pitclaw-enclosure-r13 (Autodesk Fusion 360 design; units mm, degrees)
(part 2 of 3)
extrude "Extrude8" new body sketch "J2 contact 5 profile" blind 0.12 from offset 11.78 bodies "J2 contact 5"
sketch "J2 contact 6 profile" plane through (0, 0, 0) normal (0, 0, 1) x axis (1, 0, 0)
  line L1 (22.135, 49.05) -> (21.865, 49.05)
  line L2 (22.175, 51.51) -> (22.175, 49.09)
  line L3 (21.865, 51.55) -> (22.135, 51.55)
  line L4 (21.825, 49.09) -> (21.825, 51.51)
  arc A1 centre (22.135, 49.09) radius 0.04 clockwise from (22.175, 49.09) to (22.135, 49.05)
  arc A2 centre (22.135, 51.51) radius 0.04 clockwise from (22.135, 51.55) to (22.175, 51.51)
  arc A3 centre (21.865, 51.51) radius 0.04 clockwise from (21.825, 51.51) to (21.865, 51.55)
  arc A4 centre (21.865, 49.09) radius 0.04 clockwise from (21.865, 49.05) to (21.825, 49.09)
extrude "Extrude9" new body sketch "J2 contact 6 profile" blind 0.12 from offset 11.78 bodies "J2 contact 6"
sketch "J2 contact 7 profile" plane through (0, 0, 0) normal (0, 0, 1) x axis (1, 0, 0)
  line L1 (23.155, 49.05) -> (22.885, 49.05)
  line L2 (23.195, 51.51) -> (23.195, 49.09)
  line L3 (22.885, 51.55) -> (23.155, 51.55)
  line L4 (22.845, 49.09) -> (22.845, 51.51)
  arc A1 centre (23.155, 49.09) radius 0.04 clockwise from (23.195, 49.09) to (23.155, 49.05)
  arc A2 centre (23.155, 51.51) radius 0.04 clockwise from (23.155, 51.55) to (23.195, 51.51)
  arc A3 centre (22.885, 51.51) radius 0.04 clockwise from (22.845, 51.51) to (22.885, 51.55)
  arc A4 centre (22.885, 49.09) radius 0.04 clockwise from (22.885, 49.05) to (22.845, 49.09)
extrude "Extrude10" new body sketch "J2 contact 7 profile" blind 0.12 from offset 11.78 bodies "J2 contact 7"
sketch "J2 contact 8 profile" plane through (0, 0, 0) normal (0, 0, 1) x axis (1, 0, 0)
  line L1 (24.175, 49.05) -> (23.905, 49.05)
  line L2 (24.215, 51.51) -> (24.215, 49.09)
  line L3 (23.905, 51.55) -> (24.175, 51.55)
  line L4 (23.865, 49.09) -> (23.865, 51.51)
  arc A1 centre (24.175, 49.09) radius 0.04 clockwise from (24.215, 49.09) to (24.175, 49.05)
  arc A2 centre (24.175, 51.51) radius 0.04 clockwise from (24.175, 51.55) to (24.215, 51.51)
  arc A3 centre (23.905, 51.51) radius 0.04 clockwise from (23.865, 51.51) to (23.905, 51.55)
  arc A4 centre (23.905, 49.09) radius 0.04 clockwise from (23.905, 49.05) to (23.865, 49.09)
extrude "Extrude11" new body sketch "J2 contact 8 profile" blind 0.12 from offset 11.78 bodies "J2 contact 8"
sketch "J2 leads profile" plane through (0, 0, 0) normal (0, 0, 1) x axis (1, 0, 0)
  circle C1 centre (16.94, 44.38) radius 0.275
  circle C2 centre (17.956, 42.6) radius 0.275
  circle C3 centre (18.972, 44.38) radius 0.275
  circle C4 centre (19.988, 42.6) radius 0.275
  circle C5 centre (21.004, 44.38) radius 0.275
  circle C6 centre (22.02, 42.6) radius 0.275
  circle C7 centre (23.036, 44.38) radius 0.275
  circle C8 centre (24.052, 42.6) radius 0.275
extrude "Extrude12" new body sketch "J2 leads profile" blind 3.5 from offset 6.5 bodies "J2 leads", "J2 leads (1)", "J2 leads (2)", "J2 leads (3)", "J2 leads (4)", "J2 leads (5)", "J2 leads (6)", "J2 leads (7)"
sketch "J9 barrel housing profile" plane through (0, 0, 0) normal (0, 0, 1) x axis (1, 0, 0)
  line L1 (7.85, 37.6) -> (-0.85, 37.6)
  line L2 (8, 51.85) -> (8, 37.75)
  line L3 (-0.85, 52) -> (7.85, 52)
  line L4 (-1, 37.75) -> (-1, 51.85)
  arc A1 centre (7.85, 37.75) radius 0.15 clockwise from (8, 37.75) to (7.85, 37.6)
  arc A2 centre (7.85, 51.85) radius 0.15 clockwise from (7.85, 52) to (8, 51.85)
  arc A3 centre (-0.85, 51.85) radius 0.15 clockwise from (-1, 51.85) to (-0.85, 52)
  arc A4 centre (-0.85, 37.75) radius 0.15 clockwise from (-0.85, 37.6) to (-1, 37.75)
extrude "Extrude1" new body sketch "J9 barrel housing profile" blind 10.8 from offset 9.1 bodies "J9 barrel housing"
sketch "J9 barrel opening profile" plane through (0, 0, 0) normal (0, 1, 0) x axis (1, 0, 0)
  circle C1 centre (3.5, -15.6) radius 3.15
extrude "Extrude2" cut sketch "J9 barrel opening profile" blind 3.55 from offset 48.5
sketch "J9 center pin profile" plane through (0, 0, 0) normal (0, 1, 0) x axis (1, 0, 0)
  circle C1 centre (3.5, -15.6) radius 1.05
extrude "Extrude3" new body sketch "J9 center pin profile" blind 2.6 from offset 49 bodies "J9 center pin"
sketch "J9 leads profile" plane through (0, 0, 0) normal (0, 0, 1) x axis (1, 0, 0)
  circle C1 centre (3.5, 38.4) radius 0.325
  circle C2 centre (3.5, 44.3) radius 0.325
  circle C3 centre (-1.2, 41.2) radius 0.325
extrude "Extrude4" new body sketch "J9 leads profile" blind 3.5 from offset 6.5 bodies "J9 leads", "J9 leads (1)", "J9 leads (2)"
sketch "J4 jack housing profile" plane through (0, 0, 0) normal (0, 0, 1) x axis (1, 0, 0)
  line L1 (19.4, -41.5) -> (14.6, -41.5)
  line L2 (19.55, -33.65) -> (19.55, -41.35)
  line L3 (14.6, -33.5) -> (19.4, -33.5)
  line L4 (14.45, -41.35) -> (14.45, -33.65)
  arc A1 centre (19.4, -41.35) radius 0.15 clockwise from (19.55, -41.35) to (19.4, -41.5)
  arc A2 centre (19.4, -33.65) radius 0.15 clockwise from (19.4, -33.5) to (19.55, -33.65)
  arc A3 centre (14.6, -33.65) radius 0.15 clockwise from (14.45, -33.65) to (14.6, -33.5)
  arc A4 centre (14.6, -41.35) radius 0.15 clockwise from (14.6, -41.5) to (14.45, -41.35)
extrude "Extrude1" new body sketch "J4 jack housing profile" blind 5.1 from offset 9.1 bodies "J4 jack housing"
sketch "J4 front collar profile" plane through (0, 0, 0) normal (0, 1, 0) x axis (1, 0, 0)
  circle C1 centre (17, -11.65) radius 2
extrude "Extrude2" new body sketch "J4 front collar profile" blind 3.1 from offset -44.5 bodies "J4 front collar"
sketch "J4 2.5mm plug bore profile" plane through (0, 0, 0) normal (0, 1, 0) x axis (1, 0, 0)
  circle C1 centre (17, -11.65) radius 1.25
extrude "Extrude3" cut sketch "J4 2.5mm plug bore profile" blind 3.3 from offset -44.52
sketch "J4 leads profile" plane through (0, 0, 0) normal (0, 0, 1) x axis (1, 0, 0)
  circle C1 centre (17, -33.4) radius 0.275
  circle C2 centre (18.8, -35.5) radius 0.275
  circle C3 centre (15.2, -35.5) radius 0.275
extrude "Extrude4" new body sketch "J4 leads profile" blind 3.5 from offset 6.5 bodies "J4 leads", "J4 leads (1)", "J4 leads (2)"
sketch "J5 jack housing profile" plane through (0, 0, 0) normal (0, 0, 1) x axis (1, 0, 0)
  line L1 (2.4, -41.5) -> (-2.4, -41.5)
  line L2 (2.55, -33.65) -> (2.55, -41.35)
  line L3 (-2.4, -33.5) -> (2.4, -33.5)
  line L4 (-2.55, -41.35) -> (-2.55, -33.65)
  arc A1 centre (2.4, -41.35) radius 0.15 clockwise from (2.55, -41.35) to (2.4, -41.5)
  arc A2 centre (2.4, -33.65) radius 0.15 clockwise from (2.4, -33.5) to (2.55, -33.65)
  arc A3 centre (-2.4, -33.65) radius 0.15 clockwise from (-2.55, -33.65) to (-2.4, -33.5)
  arc A4 centre (-2.4, -41.35) radius 0.15 clockwise from (-2.4, -41.5) to (-2.55, -41.35)
extrude "Extrude1" new body sketch "J5 jack housing profile" blind 5.1 from offset 9.1 bodies "J5 jack housing"
sketch "J5 front collar profile" plane through (0, 0, 0) normal (0, 1, 0) x axis (1, 0, 0)
  circle C1 centre (0, -11.65) radius 2
extrude "Extrude2" new body sketch "J5 front collar profile" blind 3.1 from offset -44.5 bodies "J5 front collar"
sketch "J5 2.5mm plug bore profile" plane through (0, 0, 0) normal (0, 1, 0) x axis (1, 0, 0)
  circle C1 centre (0, -11.65) radius 1.25
extrude "Extrude3" cut sketch "J5 2.5mm plug bore profile" blind 3.3 from offset -44.52
sketch "J5 leads profile" plane through (0, 0, 0) normal (0, 0, 1) x axis (1, 0, 0)
  circle C1 centre (0, -33.4) radius 0.275
  circle C2 centre (1.8, -35.5) radius 0.275
  circle C3 centre (-1.8, -35.5) radius 0.275
extrude "Extrude4" new body sketch "J5 leads profile" blind 3.5 from offset 6.5 bodies "J5 leads", "J5 leads (1)", "J5 leads (2)"
sketch "J6 jack housing profile" plane through (0, 0, 0) normal (0, 0, 1) x axis (1, 0, 0)
  line L1 (-14.6, -41.5) -> (-19.4, -41.5)
  line L2 (-14.45, -33.65) -> (-14.45, -41.35)
  line L3 (-19.4, -33.5) -> (-14.6, -33.5)
  line L4 (-19.55, -41.35) -> (-19.55, -33.65)
  arc A1 centre (-14.6, -41.35) radius 0.15 clockwise from (-14.45, -41.35) to (-14.6, -41.5)
  arc A2 centre (-14.6, -33.65) radius 0.15 clockwise from (-14.6, -33.5) to (-14.45, -33.65)
  arc A3 centre (-19.4, -33.65) radius 0.15 clockwise from (-19.55, -33.65) to (-19.4, -33.5)
  arc A4 centre (-19.4, -41.35) radius 0.15 clockwise from (-19.4, -41.5) to (-19.55, -41.35)
extrude "Extrude1" new body sketch "J6 jack housing profile" blind 5.1 from offset 9.1 bodies "J6 jack housing"
sketch "J6 front collar profile" plane through (0, 0, 0) normal (0, 1, 0) x axis (1, 0, 0)
  circle C1 centre (-17, -11.65) radius 2
extrude "Extrude2" new body sketch "J6 front collar profile" blind 3.1 from offset -44.5 bodies "J6 front collar"
sketch "J6 2.5mm plug bore profile" plane through (0, 0, 0) normal (0, 1, 0) x axis (1, 0, 0)
  circle C1 centre (-17, -11.65) radius 1.25
extrude "Extrude3" cut sketch "J6 2.5mm plug bore profile" blind 3.3 from offset -44.52
sketch "J6 leads profile" plane through (0, 0, 0) normal (0, 0, 1) x axis (1, 0, 0)
  circle C1 centre (-17, -33.4) radius 0.275
  circle C2 centre (-15.2, -35.5) radius 0.275
  circle C3 centre (-18.8, -35.5) radius 0.275
extrude "Extrude4" new body sketch "J6 leads profile" blind 3.5 from offset 6.5 bodies "J6 leads", "J6 leads (1)", "J6 leads (2)"
sketch "J8 female socket profile" plane through (0, 0, 0) normal (0, 0, 1) x axis (1, 0, 0)
  line L1 (18.12, -9.77) -> (-6.98, -9.77)
  line L2 (18.27, -7.38) -> (18.27, -9.62)
  line L3 (-6.98, -7.23) -> (18.12, -7.23)
  line L4 (-7.13, -9.62) -> (-7.13, -7.38)
  arc A1 centre (18.12, -9.62) radius 0.15 clockwise from (18.27, -9.62) to (18.12, -9.77)
  arc A2 centre (18.12, -7.38) radius 0.15 clockwise from (18.12, -7.23) to (18.27, -7.38)
  arc A3 centre (-6.98, -7.38) radius 0.15 clockwise from (-7.13, -7.38) to (-6.98, -7.23)
  arc A4 centre (-6.98, -9.62) radius 0.15 clockwise from (-6.98, -9.77) to (-7.13, -9.62)
extrude "Extrude1" new body sketch "J8 female socket profile" blind 8.5 from offset 9.1 bodies "J8 female socket"
sketch "J8 socket receptacles profile" plane through (0, 0, 0) normal (0, 0, 1) x axis (1, 0, 0)
  circle C1 centre (17, -8.5) radius 0.575
  circle C2 centre (14.46, -8.5) radius 0.575
  circle C3 centre (11.92, -8.5) radius 0.575
  circle C4 centre (9.38, -8.5) radius 0.575
  circle C5 centre (6.84, -8.5) radius 0.575
  circle C6 centre (4.3, -8.5) radius 0.575
  circle C7 centre (1.76, -8.5) radius 0.575
  circle C8 centre (-0.78, -8.5) radius 0.575
  circle C9 centre (-3.32, -8.5) radius 0.575
  circle C10 centre (-5.86, -8.5) radius 0.575
extrude "Extrude2" cut sketch "J8 socket receptacles profile" blind 0.82 from offset 16.8
sketch "ADS1115 blue module PCB profile" plane through (0, 0, 0) normal (0, 0, 1) x axis (1, 0, 0)
  line L1 (19.24, -24) -> (-8.16, -24)
  line L2 (19.54, -7.3) -> (19.54, -23.7)
  line L3 (-8.16, -7) -> (19.24, -7)
  line L4 (-8.46, -23.7) -> (-8.46, -7.3)
  arc A1 centre (19.24, -23.7) radius 0.3 clockwise from (19.54, -23.7) to (19.24, -24)
  arc A2 centre (19.24, -7.3) radius 0.3 clockwise from (19.24, -7) to (19.54, -7.3)
  arc A3 centre (-8.16, -7.3) radius 0.3 clockwise from (-8.46, -7.3) to (-8.16, -7)
  arc A4 centre (-8.16, -23.7) radius 0.3 clockwise from (-8.16, -24) to (-8.46, -23.7)
extrude "Extrude3" new body sketch "ADS1115 blue module PCB profile" blind 1.6 from offset 17.6 bodies "ADS1115 blue module PCB"
sketch "ADS1115 IC visual body profile" plane through (0, 0, 0) normal (0, 0, 1) x axis (1, 0, 0)
  line L1 (7.92, -19.5) -> (3.16, -19.5)
  line L2 (8.04, -15.62) -> (8.04, -19.38)
  line L3 (3.16, -15.5) -> (7.92, -15.5)
  line L4 (3.04, -19.38) -> (3.04, -15.62)
  arc A1 centre (7.92, -19.38) radius 0.12 clockwise from (8.04, -19.38) to (7.92, -19.5)
  arc A2 centre (7.92, -15.62) radius 0.12 clockwise from (7.92, -15.5) to (8.04, -15.62)
  arc A3 centre (3.16, -15.62) radius 0.12 clockwise from (3.04, -15.62) to (3.16, -15.5)
  arc A4 centre (3.16, -19.38) radius 0.12 clockwise from (3.16, -19.5) to (3.04, -19.38)
extrude "Extrude4" new body sketch "ADS1115 IC visual body profile" blind 1.2 from offset 19.2 bodies "ADS1115 IC visual body"
sketch "ADC header pin profile" plane through (0, 0, 0) normal (0, 0, 1) x axis (1, 0, 0)
  circle C1 centre (17, -8.5) radius 0.32
extrude "Extrude5" new body sketch "ADC header pin profile" blind 12.5 from offset 7 bodies "ADC header pin"
sketch "ADC header pin profile (1)" plane through (0, 0, 0) normal (0, 0, 1) x axis (1, 0, 0)
  circle C1 centre (14.46, -8.5) radius 0.32
extrude "Extrude6" new body sketch "ADC header pin profile (1)" blind 12.5 from offset 7 bodies "ADC header pin (1)"
sketch "ADC header pin profile (2)" plane through (0, 0, 0) normal (0, 0, 1) x axis (1, 0, 0)
  circle C1 centre (11.92, -8.5) radius 0.32
extrude "Extrude7" new body sketch "ADC header pin profile (2)" blind 12.5 from offset 7 bodies "ADC header pin (2)"
sketch "ADC header pin profile (3)" plane through (0, 0, 0) normal (0, 0, 1) x axis (1, 0, 0)
  circle C1 centre (9.38, -8.5) radius 0.32
extrude "Extrude8" new body sketch "ADC header pin profile (3)" blind 12.5 from offset 7 bodies "ADC header pin (3)"
sketch "ADC header pin profile (4)" plane through (0, 0, 0) normal (0, 0, 1) x axis (1, 0, 0)
  circle C1 centre (6.84, -8.5) radius 0.32
extrude "Extrude9" new body sketch "ADC header pin profile (4)" blind 12.5 from offset 7 bodies "ADC header pin (4)"
sketch "ADC header pin profile (5)" plane through (0, 0, 0) normal (0, 0, 1) x axis (1, 0, 0)
  circle C1 centre (4.3, -8.5) radius 0.32
extrude "Extrude10" new body sketch "ADC header pin profile (5)" blind 12.5 from offset 7 bodies "ADC header pin (5)"
sketch "ADC header pin profile (6)" plane through (0, 0, 0) normal (0, 0, 1) x axis (1, 0, 0)
  circle C1 centre (1.76, -8.5) radius 0.32
extrude "Extrude11" new body sketch "ADC header pin profile (6)" blind 12.5 from offset 7 bodies "ADC header pin (6)"
sketch "ADC header pin profile (7)" plane through (0, 0, 0) normal (0, 0, 1) x axis (1, 0, 0)
  circle C1 centre (-0.78, -8.5) radius 0.32
extrude "Extrude12" new body sketch "ADC header pin profile (7)" blind 12.5 from offset 7 bodies "ADC header pin (7)"
sketch "ADC header pin profile (8)" plane through (0, 0, 0) normal (0, 0, 1) x axis (1, 0, 0)
  circle C1 centre (-3.32, -8.5) radius 0.32
extrude "Extrude13" new body sketch "ADC header pin profile (8)" blind 12.5 from offset 7 bodies "ADC header pin (8)"
sketch "ADC header pin profile (9)" plane through (0, 0, 0) normal (0, 0, 1) x axis (1, 0, 0)
  circle C1 centre (-5.86, -8.5) radius 0.32
extrude "Extrude14" new body sketch "ADC header pin profile (9)" blind 12.5 from offset 7 bodies "ADC header pin (9)"
sketch "Adafruit5807 PCB profile" plane through (0, 0, 0) normal (0, 0, 1) x axis (1, 0, 0)
  line L1 (-4.54, 25.362) -> (-24.46, 25.362)
  line L2 (-4.34, 48.657) -> (-4.34, 25.562)
  line L3 (-24.46, 48.857) -> (-4.54, 48.857)
  line L4 (-24.66, 25.562) -> (-24.66, 48.657)
  arc A1 centre (-4.54, 25.562) radius 0.2 clockwise from (-4.34, 25.562) to (-4.54, 25.362)
  arc A2 centre (-4.54, 48.657) radius 0.2 clockwise from (-4.54, 48.857) to (-4.34, 48.657)
  arc A3 centre (-24.46, 48.657) radius 0.2 clockwise from (-24.66, 48.657) to (-24.46, 48.857)
  arc A4 centre (-24.46, 25.562) radius 0.2 clockwise from (-24.46, 25.362) to (-24.66, 25.562)
extrude "Extrude1" new body sketch "Adafruit5807 PCB profile" blind 1.6 from offset 12.1 bodies "Adafruit5807 PCB"
sketch "5807 M2 mounting holes profile" plane through (0, 0, 0) normal (0, 0, 1) x axis (1, 0, 0)
  circle C1 centre (-6.753, 46.317) radius 1.25
  circle C2 centre (-21.993, 46.317) radius 1.25
extrude "Extrude2" cut sketch "5807 M2 mounting holes profile" blind 1.64 from offset 12.08
sketch "3mm nylon spacer profile" plane through (0, 0, 0) normal (0, 0, 1) x axis (1, 0, 0)
  circle C1 centre (-6.753, 46.317) radius 2.5
extrude "Extrude3" new body sketch "3mm nylon spacer profile" blind 3 from offset 9.1 bodies "3mm nylon spacer"
sketch "M2 head washer profile" plane through (0, 0, 0) normal (0, 0, 1) x axis (1, 0, 0)
  circle C1 centre (-6.753, 46.317) radius 2.5
extrude "Extrude4" new body sketch "M2 head washer profile" blind 0.3 from offset 13.7 bodies "M2 head washer"
sketch "M2 screw head profile" plane through (0, 0, 0) normal (0, 0, 1) x axis (1, 0, 0)
  circle C1 centre (-6.753, 46.317) radius 2
extrude "Extrude5" new body sketch "M2 screw head profile" blind 1.5 from offset 14 bodies "M2 screw head"
sketch "3mm nylon spacer profile (1)" plane through (0, 0, 0) normal (0, 0, 1) x axis (1, 0, 0)
  circle C1 centre (-21.993, 46.317) radius 2.5
extrude "Extrude6" new body sketch "3mm nylon spacer profile (1)" blind 3 from offset 9.1 bodies "3mm nylon spacer (1)"
sketch "M2 head washer profile (1)" plane through (0, 0, 0) normal (0, 0, 1) x axis (1, 0, 0)
  circle C1 centre (-21.993, 46.317) radius 2.5
extrude "Extrude7" new body sketch "M2 head washer profile (1)" blind 0.3 from offset 13.7 bodies "M2 head washer (1)"
sketch "M2 screw head profile (1)" plane through (0, 0, 0) normal (0, 0, 1) x axis (1, 0, 0)
  circle C1 centre (-21.993, 46.317) radius 2
extrude "Extrude8" new body sketch "M2 screw head profile (1)" blind 1.5 from offset 14 bodies "M2 screw head (1)"
sketch "USB-C metal shell profile" plane through (0, 0, 0) normal (0, 1, 0) x axis (1, 0, 0)
  line L1 (-11.23, -13.6) -> (-17.77, -13.6)
  line L2 (-10.03, -15.6) -> (-10.03, -14.8)
  line L3 (-17.77, -16.8) -> (-11.23, -16.8)
  line L4 (-18.97, -14.8) -> (-18.97, -15.6)
  arc A1 centre (-11.23, -14.8) radius 1.2 clockwise from (-11.23, -13.6) to (-10.03, -14.8)
  arc A2 centre (-11.23, -15.6) radius 1.2 clockwise from (-10.03, -15.6) to (-11.23, -16.8)
  arc A3 centre (-17.77, -15.6) radius 1.2 clockwise from (-17.77, -16.8) to (-18.97, -15.6)
  arc A4 centre (-17.77, -14.8) radius 1.2 clockwise from (-18.97, -14.8) to (-17.77, -13.6)
extrude "Extrude9" new body sketch "USB-C metal shell profile" blind 7.5 from offset 42.5 bodies "USB-C metal shell"
sketch "USB-C mouth profile" plane through (0, 0, 0) normal (0, 1, 0) x axis (1, 0, 0)
  line L1 (-11.65, -14.2) -> (-17.35, -14.2)
  line L2 (-10.75, -15.3) -> (-10.75, -15.1)
  line L3 (-17.35, -16.2) -> (-11.65, -16.2)
  line L4 (-18.25, -15.1) -> (-18.25, -15.3)
  arc A1 centre (-11.65, -15.1) radius 0.9 clockwise from (-11.65, -14.2) to (-10.75, -15.1)
  arc A2 centre (-11.65, -15.3) radius 0.9 clockwise from (-10.75, -15.3) to (-11.65, -16.2)
  arc A3 centre (-17.35, -15.3) radius 0.9 clockwise from (-17.35, -16.2) to (-18.25, -15.3)
  arc A4 centre (-17.35, -15.1) radius 0.9 clockwise from (-18.25, -15.1) to (-17.35, -14.2)
extrude "Extrude10" cut sketch "USB-C mouth profile" blind 2.02 from offset 48
sketch "USB-C inner tongue profile" plane through (0, 0, 0) normal (0, 0, 1) x axis (1, 0, 0)
  line L1 (-11.52, 48.1) -> (-17.48, 48.1)
  line L2 (-11.4, 49.78) -> (-11.4, 48.22)
  line L3 (-17.48, 49.9) -> (-11.52, 49.9)
  line L4 (-17.6, 48.22) -> (-17.6, 49.78)
  arc A1 centre (-11.52, 48.22) radius 0.12 clockwise from (-11.4, 48.22) to (-11.52, 48.1)
  arc A2 centre (-11.52, 49.78) radius 0.12 clockwise from (-11.52, 49.9) to (-11.4, 49.78)
  arc A3 centre (-17.48, 49.78) radius 0.12 clockwise from (-17.6, 49.78) to (-17.48, 49.9)
  arc A4 centre (-17.48, 48.22) radius 0.12 clockwise from (-17.48, 48.1) to (-17.6, 48.22)
extrude "Extrude11" new body sketch "USB-C inner tongue profile" blind 0.5 from offset 14.95 bodies "USB-C inner tongue"
position "Position1"
sketch "Probe recess backing profile" plane through (0, 0, 0) normal (0, 1, 0) x axis (1, 0, 0)
  line L1 (28, -1.65) -> (-28, -1.65)
  line L2 (32, -17.65) -> (32, -5.65)
  line L3 (-28, -21.65) -> (28, -21.65)
  line L4 (-32, -5.65) -> (-32, -17.65)
  arc A1 centre (28, -5.65) radius 4 clockwise from (28, -1.65) to (32, -5.65)
  arc A2 centre (28, -17.65) radius 4 clockwise from (32, -17.65) to (28, -21.65)
  arc A3 centre (-28, -17.65) radius 4 clockwise from (-28, -21.65) to (-32, -17.65)
  arc A4 centre (-28, -5.65) radius 4 clockwise from (-32, -5.65) to (-28, -1.65)
extrude "Extrude18" add sketch "Probe recess backing profile" blind 9.5 from offset -52
work_plane "WorkPlane1" AlongDistance -52.02 ExtraOffset 0
sketch "Outer lip with cable clearance profile" plane through (0, -52.02, 0) normal (0, 1, 0) x axis (1, 0, 0)
  line L1 (24.5, -1.65) -> (-24.5, -1.65)
  line L2 (30, -15.15) -> (30, -7.15)
  line L3 (-24.5, -20.65) -> (24.5, -20.65)
  line L4 (-30, -7.15) -> (-30, -15.15)
  arc A1 centre (24.5, -7.15) radius 5.5 clockwise from (24.5, -1.65) to (30, -7.15)
  arc A2 centre (24.5, -15.15) radius 5.5 clockwise from (30, -15.15) to (24.5, -20.65)
  arc A3 centre (-24.5, -15.15) radius 5.5 clockwise from (-24.5, -20.65) to (-30, -15.15)
  arc A4 centre (-24.5, -7.15) radius 5.5 clockwise from (-30, -7.15) to (-24.5, -1.65)
work_plane "WorkPlane2" AlongDistance -44.5 ExtraOffset 0
sketch "Probe pocket floor profile" plane through (0, -44.5, 0) normal (0, 1, 0) x axis (1, 0, 0)
  line L1 (22, -5.65) -> (-22, -5.65)
  line L2 (25, -14.65) -> (25, -8.65)
  line L3 (-22, -17.65) -> (22, -17.65)
  line L4 (-25, -8.65) -> (-25, -14.65)
  arc A1 centre (22, -8.65) radius 3 clockwise from (22, -5.65) to (25, -8.65)
  arc A2 centre (22, -14.65) radius 3 clockwise from (25, -14.65) to (22, -17.65)
  arc A3 centre (-22, -14.65) radius 3 clockwise from (-22, -17.65) to (-25, -14.65)
  arc A4 centre (-22, -8.65) radius 3 clockwise from (-25, -8.65) to (-22, -5.65)
loft "Loft1" sketch "Outer lip with cable clearance profile" + "Probe pocket floor profile"
copy_paste_bodies "CopyPasteBodies1"
sketch "Fascia boundary profile" plane through (0, 0, 0) normal (0, 0, 1) x axis (1, 0, 0)
  line L1 (33, -53) -> (-33, -53)
  line L2 (33, -42.5) -> (33, -53)
  line L3 (-33, -42.5) -> (33, -42.5)
  line L4 (-33, -53) -> (-33, -42.5)
extrude "Extrude1" sketch "Fascia boundary profile" along normal blind 27.3
sketch "Open probe end for carrier installation profile" plane through (0, 0, 0) normal (0, 0, 1) x axis (1, 0, 0)
  line L1 (33.3, -53) -> (-33.3, -53)
  line L2 (33.3, -42) -> (33.3, -53)
  line L3 (-33.3, -42) -> (33.3, -42)
  line L4 (-33.3, -53) -> (-33.3, -42)
extrude "Extrude19" cut sketch "Open probe end for carrier installation profile" blind 27.64 from offset -0.02
sketch "Open guide block -1 profile" plane through (0, 0, 0) normal (0, 0, 1) x axis (1, 0, 0)
  line L1 (-33.3, -52) -> (-39, -52)
  line L2 (-33.3, -40.5) -> (-33.3, -52)
  line L3 (-39, -40.5) -> (-33.3, -40.5)
  line L4 (-39, -52) -> (-39, -40.5)
extrude "Extrude20" add sketch "Open guide block -1 profile" along normal blind 8
sketch "Open guide block 1 profile" plane through (0, 0, 0) normal (0, 0, 1) x axis (1, 0, 0)
  line L1 (39, -52) -> (33.3, -52)
  line L2 (39, -40.5) -> (39, -52)
  line L3 (33.3, -40.5) -> (39, -40.5)
  line L4 (33.3, -52) -> (33.3, -40.5)
extrude "Extrude21" add sketch "Open guide block 1 profile" along normal blind 8
sketch "Original rounded case perimeter profile" plane through (0, 0, 0) normal (0, 0, 1) x axis (1, 0, 0)
  line L1 (38, -52) -> (-38, -52)
  line L2 (43, 47) -> (43, -47)
  line L3 (-38, 52) -> (38, 52)
  line L4 (-43, -47) -> (-43, 47)
  arc A1 centre (38, -47) radius 5 clockwise from (43, -47) to (38, -52)
  arc A2 centre (38, 47) radius 5 clockwise from (38, 52) to (43, 47)
  arc A3 centre (-38, 47) radius 5 clockwise from (-43, 47) to (-38, 52)
  arc A4 centre (-38, -47) radius 5 clockwise from (-38, -52) to (-43, -47)
extrude "Extrude22" sketch "Original rounded case perimeter profile" along normal blind 27.6
sketch "Open-top guide channel -1 profile" plane through (0, 0, 0) normal (0, 0, 1) x axis (1, 0, 0)
  line L1 (-32.7, -52.1) -> (-36.3, -52.1)
  line L2 (-32.7, -43) -> (-32.7, -52.1)
  line L3 (-36.3, -43) -> (-32.7, -43)
  line L4 (-36.3, -52.1) -> (-36.3, -43)
extrude "Extrude23" cut sketch "Open-top guide channel -1 profile" blind 4.3 from offset 3.8
sketch "Fascia side web -1 profile" plane through (0, 0, 0) normal (0, 0, 1) x axis (1, 0, 0)
  line L1 (-31, -52) -> (-33, -52)
  line L2 (-31, -42.5) -> (-31, -52)
  line L3 (-33, -42.5) -> (-31, -42.5)
  line L4 (-33, -52) -> (-33, -42.5)
extrude "Extrude2" add sketch "Fascia side web -1 profile" blind 5.52 from offset 2.48
sketch "Sliding runner -1 profile" plane through (0, 0, 0) normal (0, 0, 1) x axis (1, 0, 0)
  line L1 (-32.7, -52) -> (-36, -52)
  line L2 (-32.7, -43) -> (-32.7, -52)
  line L3 (-36, -43) -> (-32.7, -43)
  line L4 (-36, -52) -> (-36, -43)
extrude "Extrude3" add sketch "Sliding runner -1 profile" blind 2 from offset 3.8
sketch "Guide entry cover -1 profile" plane through (0, 0, 0) normal (0, 0, 1) x axis (1, 0, 0)
  line L1 (-32.7, -52) -> (-36, -52)
  line L2 (-32.7, -50.7) -> (-32.7, -52)
  line L3 (-36, -50.7) -> (-32.7, -50.7)
  line L4 (-36, -52) -> (-36, -50.7)
extrude "Extrude4" add sketch "Guide entry cover -1 profile" blind 2 from offset 5.8
sketch "Keeper support web -1 profile" plane through (0, 0, 0) normal (0, 0, 1) x axis (1, 0, 0)
  line L1 (-29, -49.5) -> (-31.3, -49.5)
  line L2 (-29, -45.5) -> (-29, -49.5)
  line L3 (-31.3, -45.5) -> (-29, -45.5)
  line L4 (-31.3, -49.5) -> (-31.3, -45.5)
extrude "Extrude5" add sketch "Keeper support web -1 profile" blind 7 from offset 18
sketch "Open-top guide channel 1 profile" plane through (0, 0, 0) normal (0, 0, 1) x axis (1, 0, 0)
  line L1 (36.3, -52.1) -> (32.7, -52.1)
  line L2 (36.3, -43) -> (36.3, -52.1)
  line L3 (32.7, -43) -> (36.3, -43)
  line L4 (32.7, -52.1) -> (32.7, -43)
extrude "Extrude24" cut sketch "Open-top guide channel 1 profile" blind 4.3 from offset 3.8
sketch "Fascia side web 1 profile" plane through (0, 0, 0) normal (0, 0, 1) x axis (1, 0, 0)
  line L1 (33, -52) -> (31, -52)
  line L2 (33, -42.5) -> (33, -52)
  line L3 (31, -42.5) -> (33, -42.5)
  line L4 (31, -52) -> (31, -42.5)
extrude "Extrude6" add sketch "Fascia side web 1 profile" blind 5.52 from offset 2.48
sketch "Sliding runner 1 profile" plane through (0, 0, 0) normal (0, 0, 1) x axis (1, 0, 0)
  line L1 (36, -52) -> (32.7, -52)
  line L2 (36, -43) -> (36, -52)
  line L3 (32.7, -43) -> (36, -43)
  line L4 (32.7, -52) -> (32.7, -43)
extrude "Extrude7" add sketch "Sliding runner 1 profile" blind 2 from offset 3.8
sketch "Guide entry cover 1 profile" plane through (0, 0, 0) normal (0, 0, 1) x axis (1, 0, 0)
  line L1 (36, -52) -> (32.7, -52)
  line L2 (36, -50.7) -> (36, -52)
  line L3 (32.7, -50.7) -> (36, -50.7)
  line L4 (32.7, -52) -> (32.7, -50.7)
extrude "Extrude8" add sketch "Guide entry cover 1 profile" blind 2 from offset 5.8
sketch "Keeper support web 1 profile" plane through (0, 0, 0) normal (0, 0, 1) x axis (1, 0, 0)
  line L1 (31.3, -49.5) -> (29, -49.5)
  line L2 (31.3, -45.5) -> (31.3, -49.5)
  line L3 (29, -45.5) -> (31.3, -45.5)
  line L4 (29, -49.5) -> (29, -45.5)
extrude "Extrude9" add sketch "Keeper support web 1 profile" blind 7 from offset 18
sketch "Reinforced keeper block -21 profile" plane through (0, 0, 0) normal (0, 0, 1) x axis (1, 0, 0)
  line L1 (-11.7, -52) -> (-30.3, -52)
  line L2 (-11.7, -45.5) -> (-11.7, -52)
  line L3 (-30.3, -45.5) -> (-11.7, -45.5)
  line L4 (-30.3, -52) -> (-30.3, -45.5)
extrude "Extrude10" add sketch "Reinforced keeper block -21 profile" blind 4.2 from offset 20.8
sketch "Open keeper notch -21 profile" plane through (0, 0, 0) normal (0, 0, 1) x axis (1, 0, 0)
  line L1 (-14.7, -50.85) -> (-27.3, -50.85)
  line L2 (-14.7, -48.25) -> (-14.7, -50.85)
  line L3 (-27.3, -48.25) -> (-14.7, -48.25)
  line L4 (-27.3, -50.85) -> (-27.3, -48.25)
extrude "Extrude11" cut sketch "Open keeper notch -21 profile" blind 6.54 from offset 20.78
sketch "Reinforced keeper block 21 profile" plane through (0, 0, 0) normal (0, 0, 1) x axis (1, 0, 0)
  line L1 (30.3, -52) -> (11.7, -52)
  line L2 (30.3, -45.5) -> (30.3, -52)
  line L3 (11.7, -45.5) -> (30.3, -45.5)
  line L4 (11.7, -52) -> (11.7, -45.5)
extrude "Extrude12" add sketch "Reinforced keeper block 21 profile" blind 4.2 from offset 20.8
sketch "Open keeper notch 21 profile" plane through (0, 0, 0) normal (0, 0, 1) x axis (1, 0, 0)
  line L1 (27.3, -50.85) -> (14.7, -50.85)
  line L2 (27.3, -48.25) -> (27.3, -50.85)
  line L3 (14.7, -48.25) -> (27.3, -48.25)
  line L4 (14.7, -50.85) -> (14.7, -48.25)
extrude "Extrude13" cut sketch "Open keeper notch 21 profile" blind 6.54 from offset 20.78
sketch "Three probe clearance bores profile" plane through (0, 0, 0) normal (0, 1, 0) x axis (1, 0, 0)
  circle C1 centre (-17, -11.65) radius 2.8
  circle C2 centre (0, -11.65) radius 2.8
  circle C3 centre (17, -11.65) radius 2.8
extrude "Extrude14" cut sketch "Three probe clearance bores profile" blind 2.04 from offset -44.52
work_plane "WorkPlane1" AlongDistance -43.1 ExtraOffset 0
sketch "Probe-17 lead-in inner profile" plane through (0, -43.1, 0) normal (0, 1, 0) x axis (1, 0, 0)
  circle C1 centre (-17, -11.65) radius 2.8
work_plane "WorkPlane2" AlongDistance -42.48 ExtraOffset 0
sketch "Probe-17 lead-in rear profile" plane through (0, -42.48, 0) normal (0, 1, 0) x axis (1, 0, 0)
  circle C1 centre (-17, -11.65) radius 3.2
loft "Loft1" sketch "Probe-17 lead-in inner profile" + "Probe-17 lead-in rear profile"
work_plane "WorkPlane3" AlongDistance -43.1 ExtraOffset 0
sketch "Probe0 lead-in inner profile" plane through (0, -43.1, 0) normal (0, 1, 0) x axis (1, 0, 0)
  circle C1 centre (0, -11.65) radius 2.8
work_plane "WorkPlane4" AlongDistance -42.48 ExtraOffset 0
sketch "Probe0 lead-in rear profile" plane through (0, -42.48, 0) normal (0, 1, 0) x axis (1, 0, 0)
  circle C1 centre (0, -11.65) radius 3.2
loft "Loft2" sketch "Probe0 lead-in inner profile" + "Probe0 lead-in rear profile"
work_plane "WorkPlane5" AlongDistance -43.1 ExtraOffset 0
sketch "Probe17 lead-in inner profile" plane through (0, -43.1, 0) normal (0, 1, 0) x axis (1, 0, 0)
  circle C1 centre (17, -11.65) radius 2.8
work_plane "WorkPlane6" AlongDistance -42.48 ExtraOffset 0
sketch "Probe17 lead-in rear profile" plane through (0, -42.48, 0) normal (0, 1, 0) x axis (1, 0, 0)
  circle C1 centre (17, -11.65) radius 3.2
loft "Loft3" sketch "Probe17 lead-in inner profile" + "Probe17 lead-in rear profile"
sketch "Keeper root web -21 profile" plane through (0, 0, 0) normal (0, 0, 1) x axis (1, 0, 0)
  line L1 (-15, -51.5) -> (-27, -51.5)
  line L2 (-15, -48.5) -> (-15, -51.5)
  line L3 (-27, -48.5) -> (-15, -48.5)
  line L4 (-27, -51.5) -> (-27, -48.5)
extrude "Extrude15" add sketch "Keeper root web -21 profile" blind 2 from offset 27.6
sketch "Wide fascia key -21 profile" plane through (0, 0, 0) normal (0, 0, 1) x axis (1, 0, 0)
  line L1 (-15, -50.6) -> (-27, -50.6)
  line L2 (-15, -48.5) -> (-15, -50.6)
  line L3 (-27, -48.5) -> (-15, -48.5)
  line L4 (-27, -50.6) -> (-27, -48.5)
extrude "Extrude16" add sketch "Wide fascia key -21 profile" blind 5.2 from offset 23.4
work_plane "WorkPlane3" AlongDistance 23 ExtraOffset 0
sketch "Key -21 entry tip profile" plane through (0, 0, 23) normal (0, 0, 1) x axis (1, 0, 0)
  line L1 (-15.4, -50.2) -> (-26.6, -50.2)
  line L2 (-15.4, -48.9) -> (-15.4, -50.2)
  line L3 (-26.6, -48.9) -> (-15.4, -48.9)
  line L4 (-26.6, -50.2) -> (-26.6, -48.9)
work_plane "WorkPlane4" AlongDistance 23.4 ExtraOffset 0
sketch "Key -21 entry full section profile" plane through (0, 0, 23.4) normal (0, 0, 1) x axis (1, 0, 0)
  line L1 (-15, -50.6) -> (-27, -50.6)
  line L2 (-15, -48.5) -> (-15, -50.6)
  line L3 (-27, -48.5) -> (-15, -48.5)
  line L4 (-27, -50.6) -> (-27, -48.5)
loft "Loft2" sketch "Key -21 entry tip profile" + "Key -21 entry full section profile"
sketch "Keeper root web 21 profile" plane through (0, 0, 0) normal (0, 0, 1) x axis (1, 0, 0)
  line L1 (27, -51.5) -> (15, -51.5)
  line L2 (27, -48.5) -> (27, -51.5)
  line L3 (15, -48.5) -> (27, -48.5)
  line L4 (15, -51.5) -> (15, -48.5)
extrude "Extrude17" add sketch "Keeper root web 21 profile" blind 2 from offset 27.6
sketch "Wide fascia key 21 profile" plane through (0, 0, 0) normal (0, 0, 1) x axis (1, 0, 0)
  line L1 (27, -50.6) -> (15, -50.6)
  line L2 (27, -48.5) -> (27, -50.6)
  line L3 (15, -48.5) -> (27, -48.5)
  line L4 (15, -50.6) -> (15, -48.5)
extrude "Extrude18" add sketch "Wide fascia key 21 profile" blind 5.2 from offset 23.4
work_plane "WorkPlane5" AlongDistance 23 ExtraOffset 0
sketch "Key 21 entry tip profile" plane through (0, 0, 23) normal (0, 0, 1) x axis (1, 0, 0)
  line L1 (26.6, -50.2) -> (15.4, -50.2)
  line L2 (26.6, -48.9) -> (26.6, -50.2)
  line L3 (15.4, -48.9) -> (26.6, -48.9)
  line L4 (15.4, -50.2) -> (15.4, -48.9)
work_plane "WorkPlane6" AlongDistance 23.4 ExtraOffset 0
sketch "Key 21 entry full section profile" plane through (0, 0, 23.4) normal (0, 0, 1) x axis (1, 0, 0)
  line L1 (27, -50.6) -> (15, -50.6)
  line L2 (27, -48.5) -> (27, -50.6)
  line L3 (15, -48.5) -> (27, -48.5)
  line L4 (15, -50.6) -> (15, -48.5)
loft "Loft3" sketch "Key 21 entry tip profile" + "Key 21 entry full section profile"
sketch "Four internal accessory mounting bosses profile" plane through (0, 0, 0) normal (0, 0, 1) x axis (1, 0, 0)
  circle C1 centre (-36, -37) radius 5
  circle C2 centre (-36, 37) radius 5
  circle C3 centre (36, -37) radius 5
  circle C4 centre (36, 37) radius 5
extrude "Extrude25" add sketch "Four internal accessory mounting bosses profile" blind 5 from offset 2.5
sketch "Mount to wall and closure web -1 -1 profile" plane through (0, 0, 0) normal (0, 0, 1) x axis (1, 0, 0)
  line L1 (-35, -37) -> (-40.7, -37)
  line L2 (-35, -28) -> (-35, -37)
  line L3 (-40.7, -28) -> (-35, -28)
  line L4 (-40.7, -37) -> (-40.7, -28)
extrude "Extrude26" add sketch "Mount to wall and closure web -1 -1 profile" blind 5 from offset 2.5
sketch "Mount to wall and closure web -1 1 profile" plane through (0, 0, 0) normal (0, 0, 1) x axis (1, 0, 0)
  line L1 (-35, 28) -> (-40.7, 28)
  line L2 (-35, 37) -> (-35, 28)
  line L3 (-40.7, 37) -> (-35, 37)
  line L4 (-40.7, 28) -> (-40.7, 37)
extrude "Extrude27" add sketch "Mount to wall and closure web -1 1 profile" blind 5 from offset 2.5
sketch "Mount to wall and closure web 1 -1 profile" plane through (0, 0, 0) normal (0, 0, 1) x axis (1, 0, 0)
  line L1 (40.7, -37) -> (35, -37)
  line L2 (40.7, -28) -> (40.7, -37)
  line L3 (35, -28) -> (40.7, -28)
  line L4 (35, -37) -> (35, -28)
extrude "Extrude28" add sketch "Mount to wall and closure web 1 -1 profile" blind 5 from offset 2.5
sketch "Mount to wall and closure web 1 1 profile" plane through (0, 0, 0) normal (0, 0, 1) x axis (1, 0, 0)
  line L1 (40.7, 28) -> (35, 28)
  line L2 (40.7, 37) -> (40.7, 28)
  line L3 (35, 37) -> (40.7, 37)
  line L4 (35, 28) -> (35, 37)
extrude "Extrude29" add sketch "Mount to wall and closure web 1 1 profile" blind 5 from offset 2.5
sketch "Inside entry M3 insert pilots profile" plane through (0, 0, 0) normal (0, 0, 1) x axis (1, 0, 0)
  circle C1 centre (-36, -37) radius 2.1
  circle C2 centre (-36, 37) radius 2.1
  circle C3 centre (36, -37) radius 2.1
  circle C4 centre (36, 37) radius 2.1
extrude "Extrude30" cut sketch "Inside entry M3 insert pilots profile" blind 5.02 from offset 2.5
sketch "External M3 screw access profile" plane through (0, 0, 0) normal (0, 0, 1) x axis (1, 0, 0)
  circle C1 centre (-36, -37) radius 1.7
  circle C2 centre (-36, 37) radius 1.7
  circle C3 centre (36, -37) radius 1.7
  circle C4 centre (36, 37) radius 1.7
extrude "Extrude31" cut sketch "External M3 screw access profile" blind 2.54 from offset -0.02
sketch "Four short M3 insert envelopes profile" plane through (0, 0, 0) normal (0, 0, 1) x axis (1, 0, 0)
  circle C1 centre (-36, -37) radius 2.5
  circle C2 centre (-36, 37) radius 2.5
  circle C3 centre (36, -37) radius 2.5
  circle C4 centre (36, 37) radius 2.5
extrude "Extrude1" new body sketch "Four short M3 insert envelopes profile" blind 4 from offset 3.5 bodies "M3Sx4 mounting insert - simplified reference", "M3Sx4 mounting insert - simplified reference (1)", "M3Sx4 mounting insert - simplified reference (2)", "M3Sx4 mounting insert - simplified reference (3)"
sketch "Nominal thread minor bores - simplified profile" plane through (0, 0, 0) normal (0, 0, 1) x axis (1, 0, 0)
  circle C1 centre (-36, -37) radius 1.25
  circle C2 centre (-36, 37) radius 1.25
  circle C3 centre (36, -37) radius 1.25
  circle C4 centre (36, 37) radius 1.25
extrude "Extrude2" cut sketch "Nominal thread minor bores - simplified profile" blind 4.04 from offset 3.48
sketch "Heat tool clearance over probe guide stop -1 profile" plane through (0, 0, 0) normal (0, 0, 1) x axis (1, 0, 0)
  line L1 (-33.3, -43) -> (-39, -43)
  line L2 (-33.3, -40.5) -> (-33.3, -43)
  line L3 (-39, -40.5) -> (-33.3, -40.5)
  line L4 (-39, -43) -> (-39, -40.5)
extrude "Extrude32" cut sketch "Heat tool clearance over probe guide stop -1 profile" blind 0.52 from offset 7.5
sketch "Heat tool clearance over probe guide stop 1 profile" plane through (0, 0, 0) normal (0, 0, 1) x axis (1, 0, 0)
  line L1 (39, -43) -> (33.3, -43)
  line L2 (39, -40.5) -> (39, -43)
  line L3 (33.3, -40.5) -> (39, -40.5)
  line L4 (33.3, -43) -> (33.3, -40.5)
extrude "Extrude33" cut sketch "Heat tool clearance over probe guide stop 1 profile" blind 0.52 from offset 7.5
sketch "Remove stepped runner and front cover -1 profile" plane through (0, 0, 0) normal (0, 0, 1) x axis (1, 0, 0)
  line L1 (-32.95, -52.02) -> (-36.02, -52.02)
  line L2 (-32.95, -42.99) -> (-32.95, -52.02)
  line L3 (-36.02, -42.99) -> (-32.95, -42.99)
  line L4 (-36.02, -52.02) -> (-36.02, -42.99)
extrude "Extrude15" cut sketch "Remove stepped runner and front cover -1 profile" blind 4.01 from offset 3.8
sketch "Continuous runner root web -1 profile" plane through (0, 0, 0) normal (0, 0, 1) x axis (1, 0, 0)
  line L1 (-31, -52) -> (-33, -52)
  line L2 (-31, -42.5) -> (-31, -52)
  line L3 (-33, -42.5) -> (-31, -42.5)
  line L4 (-33, -52) -> (-33, -42.5)
extrude "Extrude16" add sketch "Continuous runner root web -1 profile" blind 7.02 from offset 2.48
sketch "Constant full-depth runner -1 profile" plane through (0, 0, 0) normal (0, 1, 0) x axis (1, 0, 0)
  line L1 (-36, -3.8) -> (-32.7, -3.8)
  line L2 (-36, -5.8) -> (-36, -3.8)
  line L3 (-32.7, -9.1) -> (-36, -5.8)
  line L4 (-32.7, -3.8) -> (-32.7, -9.1)
extrude "Extrude17" add sketch "Constant full-depth runner -1 profile" blind 9 from offset -52
sketch "Continuous guide roof blank -1 profile" plane through (0, 0, 0) normal (0, 0, 1) x axis (1, 0, 0)
  line L1 (-33.3, -52) -> (-39, -52)
  line L2 (-33.3, -43) -> (-33.3, -52)
  line L3 (-39, -43) -> (-33.3, -43)
  line L4 (-39, -52) -> (-39, -43)
extrude "Extrude34" add sketch "Continuous guide roof blank -1 profile" blind 6.8 from offset 3.8
sketch "Remove stepped runner and front cover 1 profile" plane through (0, 0, 0) normal (0, 0, 1) x axis (1, 0, 0)
  line L1 (36.02, -52.02) -> (32.95, -52.02)
  line L2 (36.02, -42.99) -> (36.02, -52.02)
  line L3 (32.95, -42.99) -> (36.02, -42.99)
  line L4 (32.95, -52.02) -> (32.95, -42.99)
extrude "Extrude18" cut sketch "Remove stepped runner and front cover 1 profile" blind 4.01 from offset 3.8
sketch "Continuous runner root web 1 profile" plane through (0, 0, 0) normal (0, 0, 1) x axis (1, 0, 0)
  line L1 (33, -52) -> (31, -52)
  line L2 (33, -42.5) -> (33, -52)
  line L3 (31, -42.5) -> (33, -42.5)
  line L4 (31, -52) -> (31, -42.5)
extrude "Extrude19" add sketch "Continuous runner root web 1 profile" blind 7.02 from offset 2.48
sketch "Constant full-depth runner 1 profile" plane through (0, 0, 0) normal (0, 1, 0) x axis (1, 0, 0)
  line L1 (36, -3.8) -> (32.7, -3.8)
  line L2 (36, -5.8) -> (36, -3.8)
  line L3 (32.7, -9.1) -> (36, -5.8)
  line L4 (32.7, -3.8) -> (32.7, -9.1)
extrude "Extrude20" add sketch "Constant full-depth runner 1 profile" blind 9 from offset -52
sketch "Continuous guide roof blank 1 profile" plane through (0, 0, 0) normal (0, 0, 1) x axis (1, 0, 0)
  line L1 (39, -52) -> (33.3, -52)
  line L2 (39, -43) -> (39, -52)
  line L3 (33.3, -43) -> (39, -43)
  line L4 (33.3, -52) -> (33.3, -43)
extrude "Extrude35" add sketch "Continuous guide roof blank 1 profile" blind 6.8 from offset 3.8
sketch "Preserve original rounded exterior profile" plane through (0, 0, 0) normal (0, 0, 1) x axis (1, 0, 0)
  line L1 (38, -52) -> (-38, -52)
  line L2 (43, 47) -> (43, -47)
  line L3 (-38, 52) -> (38, 52)
  line L4 (-43, -47) -> (-43, 47)
  arc A1 centre (38, -47) radius 5 clockwise from (43, -47) to (38, -52)
  arc A2 centre (38, 47) radius 5 clockwise from (38, 52) to (43, 47)
  arc A3 centre (-38, 47) radius 5 clockwise from (-43, 47) to (-38, 52)
  arc A4 centre (-38, -47) radius 5 clockwise from (-38, -52) to (-43, -47)
extrude "Extrude36" sketch "Preserve original rounded exterior profile" along normal blind 27.6
sketch "Constant full-depth guide cavity -1 profile" plane through (0, 0, 0) normal (0, 1, 0) x axis (1, 0, 0)
  line L1 (-36.4, -3.8) -> (-32.7, -3.8)
  line L2 (-36.4, -5.9) -> (-36.4, -3.8)
  line L3 (-32.7, -9.6) -> (-36.4, -5.9)
  line L4 (-32.7, -3.8) -> (-32.7, -9.6)
extrude "Extrude37" cut sketch "Constant full-depth guide cavity -1 profile" blind 9.1 from offset -52.1
sketch "Constant full-depth guide cavity 1 profile" plane through (0, 0, 0) normal (0, 1, 0) x axis (1, 0, 0)
  line L1 (36.4, -3.8) -> (32.7, -3.8)
  line L2 (36.4, -5.9) -> (36.4, -3.8)
  line L3 (32.7, -9.6) -> (36.4, -5.9)
  line L4 (32.7, -3.8) -> (32.7, -9.6)
extrude "Extrude38" cut sketch "Constant full-depth guide cavity 1 profile" blind 9.1 from offset -52.1
sketch "Guide receiver refill -1 profile" plane through (0, 0, 0) normal (0, 0, 1) x axis (1, 0, 0)
  line L1 (-33.3, -52) -> (-39, -52)
  line L2 (-33.3, -43) -> (-33.3, -52)
  line L3 (-39, -43) -> (-33.3, -43)
  line L4 (-39, -52) -> (-39, -43)
extrude "Extrude39" add sketch "Guide receiver refill -1 profile" blind 6.9 from offset 3.7
sketch "Guide receiver refill 1 profile" plane through (0, 0, 0) normal (0, 0, 1) x axis (1, 0, 0)
  line L1 (39, -52) -> (33.3, -52)
  line L2 (39, -43) -> (39, -52)
  line L3 (33.3, -43) -> (39, -43)
  line L4 (33.3, -52) -> (33.3, -43)
extrude "Extrude40" add sketch "Guide receiver refill 1 profile" blind 6.9 from offset 3.7
sketch "Preserve rounded case outline profile" plane through (0, 0, 0) normal (0, 0, 1) x axis (1, 0, 0)
  line L1 (38, -52) -> (-38, -52)
  line L2 (43, 47) -> (43, -47)
  line L3 (-38, 52) -> (38, 52)
  line L4 (-43, -47) -> (-43, 47)
  arc A1 centre (38, -47) radius 5 clockwise from (43, -47) to (38, -52)
  arc A2 centre (38, 47) radius 5 clockwise from (38, 52) to (43, 47)
  arc A3 centre (-38, 47) radius 5 clockwise from (-43, 47) to (-38, 52)
  arc A4 centre (-38, -47) radius 5 clockwise from (-38, -52) to (-43, -47)
extrude "Extrude41" sketch "Preserve rounded case outline profile" along normal blind 27.6
sketch "Guide side and roof clearance -1 profile" plane through (0, 0, 0) normal (0, 1, 0) x axis (1, 0, 0)
  line L1 (-36.3, -3.8) -> (-32.7, -3.8)
  line L2 (-36.3, -6.0657) -> (-36.3, -3.8)
  line L3 (-32.7, -9.6657) -> (-36.3, -6.0657)
  line L4 (-32.7, -3.8) -> (-32.7, -9.6657)
extrude "Extrude42" cut sketch "Guide side and roof clearance -1 profile" blind 9.1 from offset -52.1
sketch "Two guide seating lands -1 profile" plane through (0, 0, 0) normal (1, 0, 0) x axis (0, 0, -1)
  line L1 (-3.5, -50.6) -> (-3.5, -52.1)
  line L2 (-3.8, -50) -> (-3.5, -50.6)
  line L3 (-3.8, -49.2) -> (-3.8, -50)
  line L4 (-3.5, -48.6) -> (-3.8, -49.2)
  line L5 (-3.5, -44.6) -> (-3.5, -48.6)
  line L6 (-3.8, -44) -> (-3.5, -44.6)
  line L7 (-3.8, -43) -> (-3.8, -44)
  line L8 (-3.82, -43) -> (-3.8, -43)
  line L9 (-3.82, -52.1) -> (-3.82, -43)
  line L10 (-3.5, -52.1) -> (-3.82, -52.1)
extrude "Extrude43" cut sketch "Two guide seating lands -1 profile" blind 3.6 from offset -36.3
sketch "Guide side and roof clearance 1 profile" plane through (0, 0, 0) normal (0, 1, 0) x axis (1, 0, 0)
  line L1 (36.3, -3.8) -> (32.7, -3.8)
  line L2 (36.3, -6.0657) -> (36.3, -3.8)
  line L3 (32.7, -9.6657) -> (36.3, -6.0657)
  line L4 (32.7, -3.8) -> (32.7, -9.6657)
extrude "Extrude44" cut sketch "Guide side and roof clearance 1 profile" blind 9.1 from offset -52.1
sketch "Two guide seating lands 1 profile" plane through (0, 0, 0) normal (1, 0, 0) x axis (0, 0, -1)
  line L1 (-3.5, -50.6) -> (-3.5, -52.1)
  line L2 (-3.8, -50) -> (-3.5, -50.6)
  line L3 (-3.8, -49.2) -> (-3.8, -50)
  line L4 (-3.5, -48.6) -> (-3.8, -49.2)
  line L5 (-3.5, -44.6) -> (-3.5, -48.6)
  line L6 (-3.8, -44) -> (-3.5, -44.6)
  line L7 (-3.8, -43) -> (-3.8, -44)
  line L8 (-3.82, -43) -> (-3.8, -43)
  line L9 (-3.82, -52.1) -> (-3.82, -43)
  line L10 (-3.5, -52.1) -> (-3.82, -52.1)
extrude "Extrude45" cut sketch "Two guide seating lands 1 profile" blind 3.6 from offset 32.7
sketch "Fascia side seam adjustment -1 profile" plane through (0, 0, 0) normal (0, 0, 1) x axis (1, 0, 0)
  line L1 (-33, -52) -> (-33.1, -52)
  line L2 (-33, -49.5) -> (-33, -52)
  line L3 (-33.1, -49.5) -> (-33, -49.5)
  line L4 (-33.1, -52) -> (-33.1, -49.5)
extrude "Extrude21" add sketch "Fascia side seam adjustment -1 profile" along normal blind 27.4
sketch "Fascia full root web width -1 profile" plane through (0, 0, 0) normal (0, 0, 1) x axis (1, 0, 0)
  line L1 (-31, -52) -> (-33.1, -52)
  line L2 (-31, -42.5) -> (-31, -52)
  line L3 (-33.1, -42.5) -> (-31, -42.5)
  line L4 (-33.1, -52) -> (-33.1, -42.5)
extrude "Extrude22" add sketch "Fascia full root web width -1 profile" blind 7.02 from offset 2.48
sketch "Fascia floor side seam adjustment -1 profile" plane through (0, 0, 0) normal (0, 0, 1) x axis (1, 0, 0)
  line L1 (-33, -52) -> (-33.1, -52)
  line L2 (-33, -42.5) -> (-33, -52)
  line L3 (-33.1, -42.5) -> (-33, -42.5)
  line L4 (-33.1, -52) -> (-33.1, -42.5)
extrude "Extrude23" add sketch "Fascia floor side seam adjustment -1 profile" along normal blind 2.5
sketch "Fascia side seam adjustment 1 profile" plane through (0, 0, 0) normal (0, 0, 1) x axis (1, 0, 0)
  line L1 (33.1, -52) -> (33, -52)
  line L2 (33.1, -49.5) -> (33.1, -52)
  line L3 (33, -49.5) -> (33.1, -49.5)
  line L4 (33, -52) -> (33, -49.5)
extrude "Extrude24" add sketch "Fascia side seam adjustment 1 profile" along normal blind 27.4
sketch "Fascia full root web width 1 profile" plane through (0, 0, 0) normal (0, 0, 1) x axis (1, 0, 0)
  line L1 (33.1, -52) -> (31, -52)
  line L2 (33.1, -42.5) -> (33.1, -52)
  line L3 (31, -42.5) -> (33.1, -42.5)
  line L4 (31, -52) -> (31, -42.5)
extrude "Extrude25" add sketch "Fascia full root web width 1 profile" blind 7.02 from offset 2.48
sketch "Fascia floor side seam adjustment 1 profile" plane through (0, 0, 0) normal (0, 0, 1) x axis (1, 0, 0)
  line L1 (33.1, -52) -> (33, -52)
  line L2 (33.1, -42.5) -> (33.1, -52)
  line L3 (33, -42.5) -> (33.1, -42.5)
  line L4 (33, -52) -> (33, -42.5)
extrude "Extrude26" add sketch "Fascia floor side seam adjustment 1 profile" along normal blind 2.5
sketch "Fascia top seam adjustment profile" plane through (0, 0, 0) normal (0, 0, 1) x axis (1, 0, 0)
  line L1 (33.1, -52) -> (-33.1, -52)
  line L2 (33.1, -49.5) -> (33.1, -52)
  line L3 (-33.1, -49.5) -> (33.1, -49.5)
  line L4 (-33.1, -52) -> (-33.1, -49.5)
extrude "Extrude27" add sketch "Fascia top seam adjustment profile" blind 0.1 from offset 27.3
sketch "Fascia floor rear joint adjustment profile" plane through (0, 0, 0) normal (0, 0, 1) x axis (1, 0, 0)
  line L1 (33.1, -42.52) -> (-33.1, -42.52)
  line L2 (33.1, -42.2) -> (33.1, -42.52)
  line L3 (-33.1, -42.2) -> (33.1, -42.2)
  line L4 (-33.1, -42.52) -> (-33.1, -42.2)
extrude "Extrude28" add sketch "Fascia floor rear joint adjustment profile" along normal blind 2.5
sketch "Keep keeper notch open through top -21 profile" plane through (0, 0, 0) normal (0, 0, 1) x axis (1, 0, 0)
  line L1 (-14.7, -50.85) -> (-27.3, -50.85)
  line L2 (-14.7, -48.25) -> (-14.7, -50.85)
  line L3 (-27.3, -48.25) -> (-14.7, -48.25)
  line L4 (-27.3, -50.85) -> (-27.3, -48.25)
extrude "Extrude29" cut sketch "Keep keeper notch open through top -21 profile" blind 6.64 from offset 20.78
sketch "Keep keeper notch open through top 21 profile" plane through (0, 0, 0) normal (0, 0, 1) x axis (1, 0, 0)
  line L1 (27.3, -50.85) -> (14.7, -50.85)
  line L2 (27.3, -48.25) -> (27.3, -50.85)
  line L3 (14.7, -48.25) -> (27.3, -48.25)
  line L4 (14.7, -50.85) -> (14.7, -48.25)
extrude "Extrude30" cut sketch "Keep keeper notch open through top 21 profile" blind 6.64 from offset 20.78
sketch "Uniform locating lip outer corner clearance profile" plane through (0, 0, 0) normal (0, 0, 1) x axis (1, 0, 0)
  line L1 (-40.2, -49.2) -> (-38, -49.2)
  line L2 (-40.2, -47) -> (-40.2, -49.2)
  line L3 (-40.2, 49.2) -> (-38, 49.2)
  line L4 (-40.2, 47) -> (-40.2, 49.2)
  line L5 (40.2, -49.2) -> (38, -49.2)
  line L6 (40.2, -47) -> (40.2, -49.2)
  line L7 (40.2, 49.2) -> (38, 49.2)
  line L8 (40.2, 47) -> (40.2, 49.2)
  arc A1 centre (-38, -47) radius 2.2 clockwise from (-38, -49.2) to (-40.2, -47)
  arc A2 centre (-38, 47) radius 2.2 clockwise from (-40.2, 47) to (-38, 49.2)
  arc A3 centre (38, -47) radius 2.2 clockwise from (40.2, -47) to (38, -49.2)
  arc A4 centre (38, 47) radius 2.2 clockwise from (38, 49.2) to (40.2, 47)
extrude "Extrude19" cut sketch "Uniform locating lip outer corner clearance profile" blind 2 from offset 25.6
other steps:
base_feature "Base Feature1" bodies "Bottom shell - corrected physical connector order", "04 Probe fascia - fitted seams"
create_component "CreateComponent1"
create_component "CreateComponent2"
create_component "CreateComponent3"
create_component "CreateComponent4"
create_component "CreateComponent5"
create_component "CreateComponent6"
create_component "CreateComponent1"
create_component "CreateComponent1"
create_component "CreateComponent2"
create_component "CreateComponent3"
create_component "CreateComponent4"
create_component "CreateComponent5"
create_component "CreateComponent6"
create_component "CreateComponent7"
